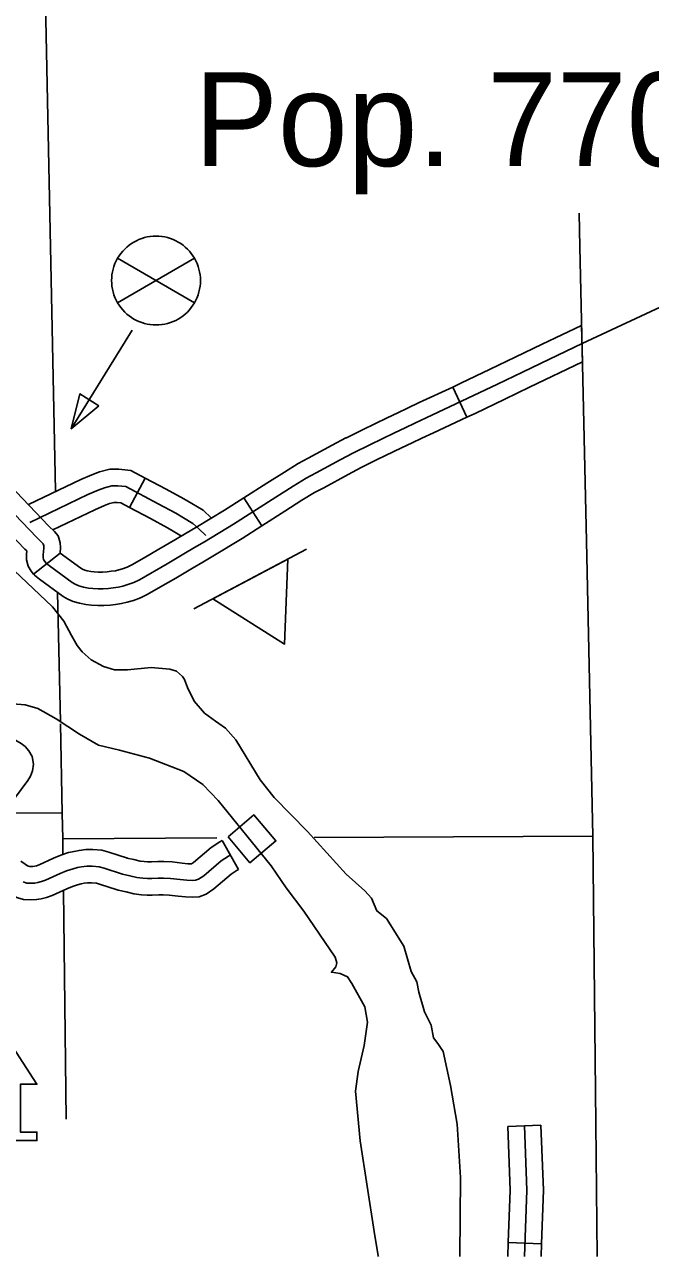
# Model space of a CAD drawing. Extents: x -3711 to 825, y -151 to 1050.
# Drawn here: x -2951.5 to -2919.9, y 120.4 to 182.5 of the extents above; entities that cross this region are included whole.
import ezdxf

# ---------------------------------------------------------------- set-up
doc = ezdxf.new("R2010")
doc.units = 0
for name, color, linetype in [('Level 31', 7, 'Continuous'), ('Level 32', 7, 'Continuous'), ('Level 33', 7, 'Continuous'), ('Level 4', 7, 'Continuous'), ('Level 5', 7, 'Continuous'), ('Level 57', 7, 'Continuous'), ('Level 6', 7, 'Continuous'), ('Level 8', 7, 'Continuous'), ('Level 9', 7, 'Continuous')]:
    doc.layers.add(name, color=color, linetype=linetype)

msp = doc.modelspace()

# ---------------------------------------------------------------- linework, layer by layer
at = {"layer": 'Level 31'}
for p, q in [((-2929.144, 162.687), (-2929.854, 164.21)), ((-2929.144, 162.687), (-2929.144, 162.687)), ((-2940.397, 158.62), (-2939.49, 157.204)), ((-2951.007, 154.776), (-2949.666, 155.834)), ((-2951.006, 154.775), (-2951.007, 154.776)), ((-2940.662, 139.872), (-2941.489, 141.336)), ((-2940.662, 139.872), (-2940.662, 139.872))]:
    msp.add_line(p, q, dxfattribs=at)
for points in [[(-2929.854, 164.21), (-2929.444, 164.402), (-2927.955, 165.113), (-2926.698, 165.717), (-2925.336, 166.367), (-2923.345, 167.321), (-2923.304, 165.474)], [(-2946.986, 154.079), (-2946.72, 154.117), (-2946.502, 154.165), (-2946.245, 154.241), (-2945.95, 154.355), (-2945.665, 154.488), (-2944.258, 155.297), (-2943.421, 155.792), (-2942.887, 156.106), (-2942.385, 156.401), (-2940.921, 157.286), (-2938.782, 158.656), (-2937.907, 159.208), (-2937.242, 159.617), (-2936.748, 159.874), (-2935.531, 160.53), (-2934.856, 160.892), (-2934.029, 161.301), (-2932.793, 161.9), (-2932.26, 162.148), (-2931.766, 162.386), (-2931.186, 162.662), (-2929.085, 163.642), (-2927.592, 164.355), (-2926.335, 164.958), (-2924.973, 165.609), (-2923.325, 166.399)], [(-2923.304, 165.474), (-2925.972, 164.2), (-2927.229, 163.597), (-2928.726, 162.881), (-2929.144, 162.687)], [(-2935.212, 161.653), (-2934.398, 162.056), (-2933.153, 162.66), (-2932.62, 162.908), (-2932.129, 163.144), (-2931.544, 163.422), (-2929.854, 164.21)], [(-2934.467, 160.146), (-2933.659, 160.546), (-2932.432, 161.141), (-2931.901, 161.388), (-2931.403, 161.627), (-2930.828, 161.901), (-2929.144, 162.687)], [(-2940.397, 158.62), (-2939.233, 159.365), (-2938.351, 159.922), (-2937.656, 160.349), (-2937.141, 160.617), (-2935.929, 161.271), (-2935.241, 161.639), (-2935.212, 161.653)], [(-2953.279, 160.373), (-2953.208, 160.289), (-2950.248, 157.214), (-2949.95, 156.922), (-2949.767, 156.703), (-2949.661, 156.348), (-2949.647, 156.107), (-2949.666, 155.834)], [(-2953.832, 159.725), (-2950.845, 156.622), (-2950.569, 156.351), (-2950.523, 156.296), (-2950.494, 156.201), (-2950.489, 156.112), (-2950.494, 156.039), (-2950.504, 155.944), (-2950.532, 155.706), (-2950.532, 155.611), (-2950.504, 155.506), (-2950.447, 155.411), (-2950.371, 155.326), (-2950.2, 155.183), (-2949.068, 154.355), (-2948.907, 154.269), (-2948.717, 154.184), (-2948.498, 154.117), (-2948.241, 154.07), (-2948.013, 154.041), (-2947.756, 154.032), (-2947.5, 154.032), (-2947.224, 154.051), (-2946.986, 154.079)], [(-2939.49, 157.204), (-2938.331, 157.947), (-2937.463, 158.495), (-2936.828, 158.885), (-2936.354, 159.131), (-2935.133, 159.79), (-2934.471, 160.144), (-2934.467, 160.146)], [(-2954.563, 159.288), (-2954.456, 159.162), (-2951.443, 156.031), (-2951.351, 155.941), (-2951.373, 155.756), (-2951.373, 155.499), (-2951.284, 155.174), (-2951.128, 154.912), (-2951.007, 154.776)], [(-2945.433, 155.591), (-2944.681, 156.023), (-2943.848, 156.516), (-2943.313, 156.83), (-2942.815, 157.123), (-2941.365, 157.999), (-2940.397, 158.62)], [(-2939.49, 157.204), (-2940.477, 156.572), (-2941.955, 155.679), (-2942.461, 155.381), (-2942.994, 155.068), (-2943.834, 154.571), (-2944.595, 154.134)], [(-2949.666, 155.834), (-2948.621, 155.069), (-2948.537, 155.025), (-2948.42, 154.972), (-2948.298, 154.935), (-2948.112, 154.901), (-2947.945, 154.88), (-2947.741, 154.872), (-2947.529, 154.872), (-2947.303, 154.888), (-2947.096, 154.913), (-2946.869, 154.945), (-2946.711, 154.98), (-2946.517, 155.037), (-2946.28, 155.129), (-2946.053, 155.235), (-2945.433, 155.591)], [(-2944.595, 154.134), (-2945.277, 153.742), (-2945.62, 153.581), (-2945.973, 153.445), (-2946.292, 153.35), (-2946.571, 153.289), (-2946.877, 153.246), (-2947.145, 153.213), (-2947.471, 153.191), (-2947.772, 153.191), (-2948.081, 153.202), (-2948.37, 153.239), (-2948.698, 153.299), (-2949.013, 153.395), (-2949.277, 153.514), (-2949.516, 153.641), (-2950.718, 154.52), (-2950.957, 154.72), (-2951.006, 154.775)], [(-2954.267, 147.812), (-2954.225, 147.774), (-2954.155, 147.715), (-2953.206, 147.14), (-2951.638, 146.227), (-2951.438, 146.07), (-2951.244, 145.858), (-2951.087, 145.569), (-2951.02, 145.188), (-2951.062, 144.85), (-2951.165, 144.574), (-2951.294, 144.355), (-2951.966, 143.445), (-2952.362, 142.815)], [(-2941.489, 141.336), (-2941.612, 141.267), (-2942.045, 140.977), (-2942.933, 140.226), (-2943.036, 140.155), (-2943.215, 140.163), (-2943.514, 140.195), (-2944.015, 140.258), (-2944.437, 140.281), (-2944.744, 140.274), (-2945.064, 140.261), (-2945.251, 140.261), (-2945.428, 140.266), (-2945.631, 140.294), (-2945.956, 140.375), (-2946.295, 140.45), (-2946.276, 140.444)], [(-2946.276, 140.444), (-2947.204, 140.744), (-2947.559, 140.838), (-2948.021, 140.873), (-2948.369, 140.873), (-2948.71, 140.837), (-2948.967, 140.786), (-2949.249, 140.72), (-2949.641, 140.589), (-2950.004, 140.437), (-2950.733, 140.113), (-2950.862, 140.061), (-2950.951, 140.041), (-2951.046, 140.025), (-2951.164, 140.018), (-2951.203, 140.02), (-2951.26, 140.038), (-2951.319, 140.061), (-2951.439, 140.143), (-2951.649, 140.291)], [(-2941.076, 140.604), (-2941.171, 140.55), (-2941.538, 140.305), (-2942.422, 139.556), (-2942.681, 139.379), (-2942.83, 139.325), (-2942.994, 139.311), (-2943.279, 139.325), (-2943.611, 139.36), (-2944.09, 139.42), (-2944.45, 139.44), (-2944.717, 139.434), (-2945.047, 139.42), (-2945.263, 139.42), (-2945.497, 139.427), (-2945.79, 139.467), (-2946.149, 139.556), (-2946.516, 139.638), (-2947.441, 139.937), (-2947.7, 140.005), (-2948.053, 140.033), (-2948.325, 140.033), (-2948.584, 140.005), (-2948.788, 139.965), (-2949.019, 139.91), (-2949.345, 139.801), (-2949.672, 139.665), (-2950.406, 139.338), (-2950.61, 139.257), (-2950.787, 139.216), (-2950.95, 139.189), (-2951.168, 139.175), (-2951.358, 139.189), (-2951.535, 139.243)], [(-2946.794, 138.844), (-2946.738, 138.826), (-2946.342, 138.738), (-2945.949, 138.64), (-2945.566, 138.588), (-2945.275, 138.58), (-2945.031, 138.58), (-2944.689, 138.593), (-2944.463, 138.599), (-2944.166, 138.583), (-2943.707, 138.525), (-2943.344, 138.486), (-2942.979, 138.469), (-2942.649, 138.496), (-2942.294, 138.626), (-2941.912, 138.887), (-2941.032, 139.632), (-2940.731, 139.833), (-2940.662, 139.872)], [(-2952.619, 138.918), (-2952.398, 138.762), (-2952.105, 138.562), (-2951.81, 138.448), (-2951.514, 138.357), (-2951.172, 138.333), (-2950.855, 138.352), (-2950.623, 138.391), (-2950.358, 138.452), (-2950.079, 138.564), (-2949.339, 138.893), (-2949.05, 139.014), (-2948.789, 139.101), (-2948.609, 139.143), (-2948.457, 139.174), (-2948.281, 139.192), (-2948.086, 139.192), (-2947.84, 139.173), (-2947.678, 139.13), (-2946.794, 138.844)]]:
    msp.add_lwpolyline(points, dxfattribs=at)
at = {"layer": 'Level 32'}
for p, q in [((-2946.162, 158.13), (-2945.372, 159.613)), ((-2927.075, 126.901), (-2925.396, 126.969)), ((-2927.048, 121.054), (-2925.368, 120.989))]:
    msp.add_line(p, q, dxfattribs=at)
for points in [[(-2951.274, 158.28), (-2948.617, 159.545), (-2948.075, 159.784), (-2947.69, 159.932), (-2947.157, 160.065), (-2946.712, 160.065), (-2946.105, 160.004), (-2945.372, 159.613)], [(-2951.207, 157.381), (-2948.267, 158.781), (-2947.754, 159.006), (-2947.436, 159.129), (-2947.054, 159.224), (-2946.754, 159.224), (-2946.354, 159.184), (-2944.719, 158.313), (-2943.836, 157.842), (-2943.446, 157.616), (-2942.964, 157.317), (-2942.692, 157.069), (-2942.317, 156.723)], [(-2945.372, 159.613), (-2944.323, 159.055), (-2943.428, 158.577), (-2943.014, 158.337), (-2942.455, 157.991), (-2942.026, 157.6)], [(-2950.045, 157.003), (-2947.916, 158.016), (-2947.433, 158.229), (-2947.182, 158.326), (-2946.95, 158.384), (-2946.796, 158.384), (-2946.603, 158.364), (-2946.162, 158.13)], [(-2946.162, 158.13), (-2945.115, 157.572), (-2944.245, 157.107), (-2943.878, 156.895), (-2943.55, 156.691)], [(-2927.075, 126.901), (-2926.946, 123.69), (-2927.048, 121.054)], [(-2926.235, 126.935), (-2926.105, 123.691), (-2926.233, 120.355)], [(-2925.396, 126.969), (-2925.264, 123.691), (-2925.368, 120.989)], [(-2927.048, 121.054), (-2927.075, 120.355)], [(-2925.368, 120.989), (-2925.392, 120.355)]]:
    msp.add_lwpolyline(points, dxfattribs=at)
at = {"layer": 'Level 33'}
msp.add_lwpolyline([(-2923.325, 166.399), (-2918.881, 168.475)], dxfattribs=at)
at = {"layer": 'Level 4'}
for points in [[(-2949.657, 147.213), (-2949.563, 142.707), (-2949.536, 141.419), (-2949.527, 140.663)], [(-2949.505, 138.801), (-2949.367, 127.278)]]:
    msp.add_lwpolyline(points, dxfattribs=at)
at = {"layer": 'Level 5'}
for points in [[(-2952.334, 142.728), (-2949.563, 142.707)], [(-2949.536, 141.419), (-2941.756, 141.46)], [(-2936.846, 141.485), (-2922.773, 141.559)]]:
    msp.add_lwpolyline(points, dxfattribs=at)
at = {"layer": 'Level 57'}
for p, q in [((-2942.886, 170.702), (-2946.769, 168.46)), ((-2946.769, 170.702), (-2942.886, 168.46)), ((-2949.104, 162.102), (-2946.036, 167.069)), ((-2937.229, 156.026), (-2942.914, 153.022))]:
    msp.add_line(p, q, dxfattribs=at)
for points in [[(-2947.71, 163.252), (-2948.679, 163.859), (-2949.104, 162.102)], [(-2938.176, 155.526), (-2941.967, 153.522), (-2938.337, 151.241)], [(-2941.195, 141.518), (-2939.885, 142.625), (-2938.778, 141.315), (-2940.087, 140.208)], [(-2955.434, 126.196), (-2950.838, 126.196), (-2950.838, 126.624), (-2951.678, 126.624), (-2951.678, 129.037), (-2950.838, 129.037), (-2953.136, 132.552), (-2955.434, 129.037), (-2954.594, 129.037), (-2954.594, 126.624), (-2955.434, 126.624)]]:
    msp.add_lwpolyline(points, close=True, dxfattribs=at)
for start, end in [(30.00001, 150.00025), (150.00025, 209.99994), (329.99999, 30.00001), (209.99994, 329.99999)]:
    msp.add_arc((-2944.828, 169.581), 2.242, start, end, dxfattribs=at)
at = {"layer": 'Level 6'}
msp.add_lwpolyline([(-2922.569, 120.355), (-2922.634, 127.076), (-2922.773, 141.559), (-2923.103, 156.433), (-2923.433, 171.286), (-2923.471, 172.983)], dxfattribs=at)
at = {"layer": 'Level 8'}
for points in [[(-2920.796, 270.225), (-2921.112, 260.629), (-2924.417, 260.676), (-2924.536, 201.01), (-2950.769, 200.81), (-2949.901, 158.971)], [(-2949.794, 153.844), (-2949.659, 147.336)]]:
    msp.add_lwpolyline(points, dxfattribs=at)
at = {"layer": 'Level 9'}
for points in [[(-2952.302, 155.261), (-2950.054, 153.119), (-2949.484, 152.405), (-2949.094, 151.67), (-2948.817, 151.175), (-2948.56, 150.859), (-2948.105, 150.443), (-2947.472, 150.107), (-2946.918, 149.948), (-2946.266, 149.948), (-2945.079, 150.067), (-2944.13, 149.968), (-2943.794, 149.869), (-2943.494, 149.607), (-2943.398, 149.454), (-2943.246, 149.05), (-2942.906, 148.369), (-2942.38, 147.75), (-2941.824, 147.348), (-2941.329, 147.007), (-2940.803, 146.419), (-2939.567, 144.389), (-2938.86, 143.499), (-2937.18, 141.793), (-2935.231, 139.634), (-2934.291, 138.794), (-2933.945, 138.422), (-2933.682, 137.778), (-2933.19, 137.398), (-2932.314, 135.997), (-2931.945, 134.717), (-2931.667, 134.209), (-2931.556, 133.677), (-2931.276, 132.682), (-2930.94, 132.026), (-2930.829, 131.382), (-2930.596, 131.096), (-2930.339, 130.688), (-2929.958, 128.971), (-2929.626, 127.016), (-2929.458, 124.329), (-2929.486, 120.355)], [(-2953.513, 148.338), (-2951.441, 148.183), (-2950.792, 147.998), (-2949.864, 147.471), (-2948.689, 146.698), (-2947.73, 146.14), (-2946.679, 145.893), (-2945.163, 145.49), (-2943.432, 144.81), (-2942.473, 144.16), (-2941.7, 143.355), (-2939.022, 140.058), (-2938.267, 138.939), (-2937.367, 137.763), (-2935.778, 135.44), (-2935.694, 135.16), (-2935.75, 134.964), (-2935.974, 134.685), (-2935.527, 134.629), (-2935.163, 134.461), (-2934.939, 134.125), (-2934.296, 132.949), (-2934.156, 132.166), (-2934.324, 130.99), (-2934.632, 129.675), (-2934.755, 128.688), (-2934.52, 126.176), (-2933.821, 121.614), (-2933.61, 120.39), (-2933.604, 120.355)]]:
    msp.add_lwpolyline(points, dxfattribs=at)

# ---------------------------------------------------------------- texts
at = {"layer": 'Level 6'}
msp.add_text('Pop. 770', height=4.7343, dxfattribs=at).set_placement((-2942.897, 175.351))

doc.saveas('drawing.dxf')
